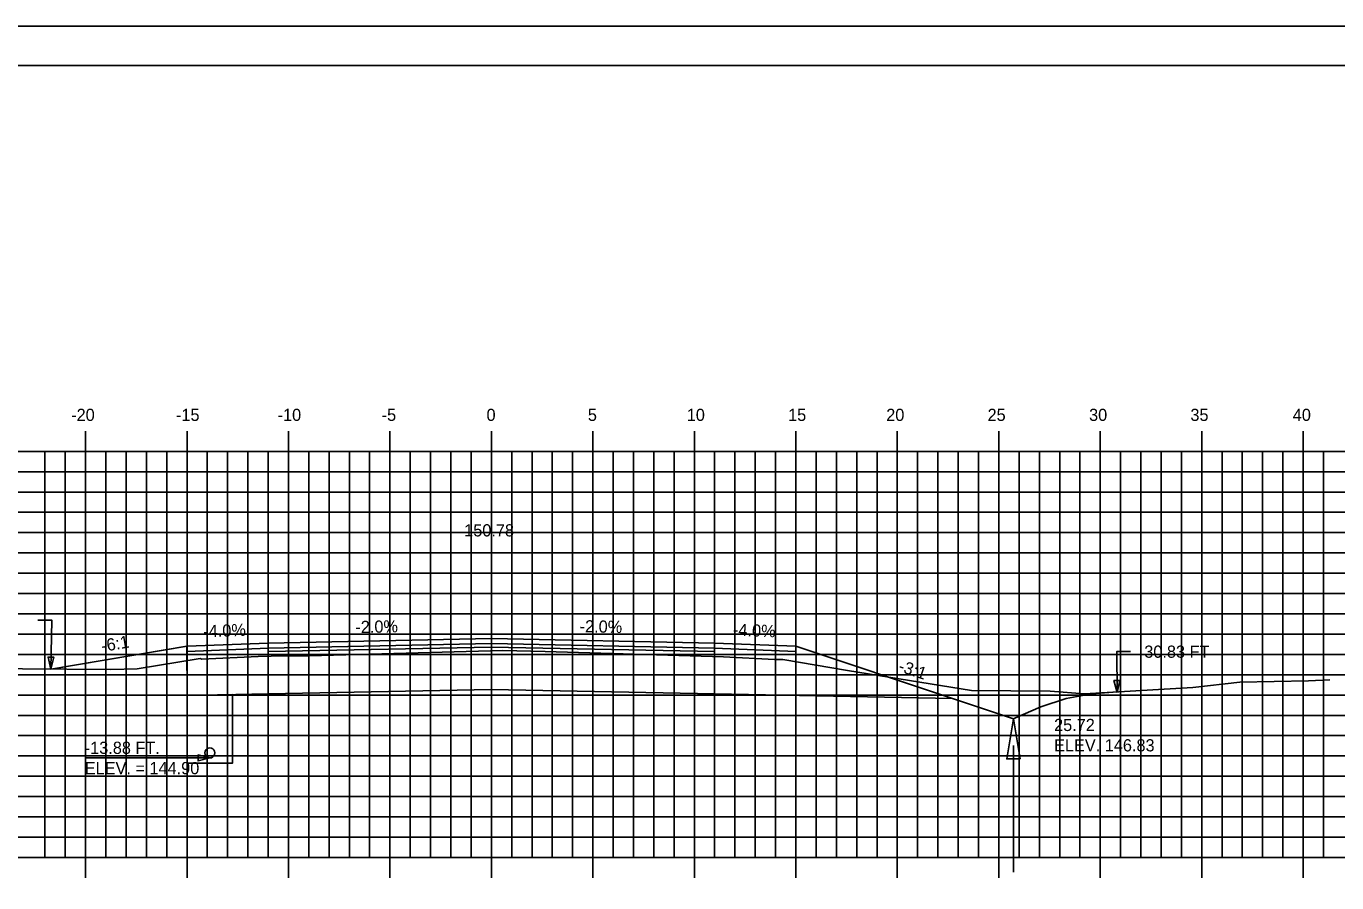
# Model space of a CAD drawing. Extents: x 1147633 to 1147803, y 608981 to 609091.
# Drawn here: x 1147693.5 to 1147758.1, y 609049.1 to 609091.3 of the extents above; entities that cross this region are included whole.
import ezdxf

# ---------------------------------------------------------------- set-up
doc = ezdxf.new("R2010")
doc.units = 0
for name, color, linetype in [('ANNOTATION', 7, 'Continuous'), ('BORDER', 7, 'Continuous'), ('D_Drainage_Ditch_Line', 7, 'Continuous'), ('D_Drainage_Underdrain', 7, 'Continuous'), ('D_Drainage_Underdrain_06in', 7, 'Continuous'), ('D_Roadway_Centerline', 7, 'Continuous'), ('D_Roadway_Centerline_Text', 7, 'Continuous'), ('D_Roadway_Edge_Shoulder', 7, 'Continuous'), ('D_Roadway_Edge_TW', 7, 'Continuous'), ('D_Roadway_Pavement', 7, 'Continuous'), ('D_Roadway_SlopeLines', 7, 'Continuous'), ('D_Roadway_SubGrade', 7, 'Continuous'), ('D_Text_Standard', 7, 'Continuous'), ('H_V ANNOTATION', 7, 'Continuous'), ('MAJOR', 7, 'Continuous'), ('MINOR', 7, 'Continuous'), ('PLOT BOUNDARY', 7, 'Continuous'), ('S_Roadway_Centerline', 7, 'Continuous')]:
    doc.layers.add(name, color=color, linetype=linetype)

msp = doc.modelspace()

# ---------------------------------------------------------------- linework, layer by layer
msp.add_lwpolyline([(1147694.741, 609059.617), (1147701.453, 609060.736), (1147701.454, 609060.736), (1147705.454, 609060.896), (1147716.454, 609061.116), (1147727.454, 609060.896), (1147731.454, 609060.736), (1147739.177, 609058.162), (1147742.177, 609057.162), (1147742.281, 609057.214), (1147743.531, 609057.762), (1147744.781, 609058.158), (1147746.031, 609058.4), (1147747.281, 609058.489)])
at = {"layer": 'BORDER'}
msp.add_lwpolyline([(1147641.454, 608984.335), (1147801.454, 608984.335), (1147801.454, 609089.335), (1147641.454, 609089.335)], close=True, dxfattribs=at)
at = {"layer": 'D_Drainage_Ditch_Line'}
msp.add_line((1147742.178, 609055.85), (1147742.177, 609049.606), dxfattribs=at)
msp.add_lwpolyline([(1147742.506, 609055.193), (1147741.849, 609055.193), (1147742.177, 609057.162)], close=True, dxfattribs=at)
at = {"layer": 'D_Drainage_Underdrain'}
msp.add_lwpolyline([(1147701.454, 609058.316), (1147701.454, 609054.986), (1147703.704, 609054.986), (1147703.704, 609058.361)], close=True, dxfattribs=at)
at = {"layer": 'D_Drainage_Underdrain_06in'}
msp.add_lwpolyline([(1147702.579, 609055.736), (1147702.656, 609055.724), (1147702.726, 609055.689), (1147702.781, 609055.633), (1147702.817, 609055.564), (1147702.829, 609055.486), (1147702.817, 609055.409), (1147702.781, 609055.339), (1147702.726, 609055.284), (1147702.656, 609055.249), (1147702.579, 609055.236), (1147702.502, 609055.249), (1147702.432, 609055.284), (1147702.377, 609055.339), (1147702.341, 609055.409), (1147702.329, 609055.486), (1147702.341, 609055.564), (1147702.377, 609055.633), (1147702.432, 609055.689), (1147702.502, 609055.724)], close=True, dxfattribs=at)
at = {"layer": 'D_Roadway_Edge_Shoulder'}
for points in [[(1147705.454, 609060.896), (1147701.454, 609060.736), (1147701.454, 609060.486), (1147705.454, 609060.646)], [(1147727.454, 609060.896), (1147731.454, 609060.736), (1147731.454, 609060.486), (1147727.454, 609060.646)]]:
    msp.add_lwpolyline(points, close=True, dxfattribs=at)
at = {"layer": 'D_Roadway_Edge_TW'}
msp.add_lwpolyline([(1147705.454, 609060.646), (1147705.454, 609060.896), (1147716.454, 609061.116), (1147727.454, 609060.896), (1147727.454, 609060.646), (1147716.454, 609060.866)], close=True, dxfattribs=at)
at = {"layer": 'D_Roadway_Pavement'}
msp.add_lwpolyline([(1147705.454, 609060.48), (1147705.454, 609060.646), (1147716.454, 609060.866), (1147727.454, 609060.646), (1147727.454, 609060.48), (1147716.454, 609060.7)], close=True, dxfattribs=at)
at = {"layer": 'D_Roadway_SlopeLines'}
for points in [[(1147701.454, 609060.736), (1147694.741, 609059.617)], [(1147739.177, 609058.162), (1147742.177, 609057.162)], [(1147742.177, 609057.162), (1147742.281, 609057.214), (1147743.531, 609057.762), (1147744.781, 609058.158), (1147746.031, 609058.4), (1147747.281, 609058.489)]]:
    msp.add_lwpolyline(points, dxfattribs=at)
at = {"layer": 'D_Roadway_SubGrade'}
for points in [[(1147705.454, 609060.48), (1147705.454, 609060.646), (1147701.454, 609060.486), (1147701.454, 609060.736), (1147701.453, 609060.736), (1147701.454, 609058.316), (1147705.454, 609058.396)], [(1147705.454, 609058.396), (1147705.454, 609060.48), (1147716.454, 609060.7), (1147727.454, 609060.48), (1147727.454, 609058.396), (1147716.454, 609058.616)], [(1147727.454, 609060.48), (1147727.454, 609060.646), (1147731.454, 609060.486), (1147731.454, 609060.736), (1147731.454, 609060.736), (1147739.177, 609058.162), (1147727.454, 609058.396)]]:
    msp.add_lwpolyline(points, close=True, dxfattribs=at)
at = {"layer": 'D_Text_Standard'}
msp.add_line((1147696.416, 609055.236), (1147700.83, 609055.236), dxfattribs=at)
for points in [[(1147694.741, 609059.617), (1147694.786, 609062.026), (1147694.106, 609062.026)], [(1147747.281, 609058.464), (1147747.263, 609060.472), (1147747.943, 609060.472)], [(1147702.579, 609055.236), (1147701.51, 609055.236), (1147700.83, 609055.236)]]:
    msp.add_lwpolyline(points, dxfattribs=at)
for points in [[(1147694.741, 609059.617), (1147694.606, 609060.202), (1147694.897, 609060.197)], [(1147747.281, 609058.464), (1147747.13, 609059.044), (1147747.421, 609059.047)], [(1147702.579, 609055.236), (1147701.997, 609055.091), (1147701.997, 609055.382)]]:
    msp.add_lwpolyline(points, close=True, dxfattribs=at)
at = {"layer": 'MAJOR'}
for p, q in [((1147696.454, 609071.337), (1147696.454, 609070.335)), ((1147701.454, 609071.337), (1147701.454, 609070.335)), ((1147706.454, 609071.337), (1147706.454, 609070.335)), ((1147711.454, 609071.337), (1147711.454, 609070.335)), ((1147716.454, 609071.337), (1147716.454, 609070.335)), ((1147721.454, 609071.337), (1147721.454, 609070.335)), ((1147726.454, 609071.337), (1147726.454, 609070.335)), ((1147731.454, 609071.337), (1147731.454, 609070.335)), ((1147736.454, 609071.337), (1147736.454, 609070.335)), ((1147741.454, 609071.337), (1147741.454, 609070.335)), ((1147746.454, 609071.337), (1147746.454, 609070.335)), ((1147751.454, 609071.337), (1147751.454, 609070.335)), ((1147756.454, 609071.337), (1147756.454, 609070.335)), ((1147646.454, 609070.335), (1147786.454, 609070.335)), ((1147646.454, 609070.335), (1147786.454, 609070.335)), ((1147696.454, 609050.335), (1147696.454, 609070.335)), ((1147701.454, 609050.335), (1147701.454, 609070.335)), ((1147706.454, 609050.335), (1147706.454, 609070.335)), ((1147711.454, 609050.335), (1147711.454, 609070.335)), ((1147716.454, 609050.335), (1147716.454, 609070.335)), ((1147721.454, 609050.335), (1147721.454, 609070.335)), ((1147726.454, 609050.335), (1147726.454, 609070.335)), ((1147731.454, 609050.335), (1147731.454, 609070.335)), ((1147736.454, 609050.335), (1147736.454, 609070.335)), ((1147741.454, 609050.335), (1147741.454, 609070.335)), ((1147746.454, 609050.335), (1147746.454, 609070.335)), ((1147751.454, 609050.335), (1147751.454, 609070.335)), ((1147756.454, 609050.335), (1147756.454, 609070.335)), ((1147646.454, 609065.335), (1147786.454, 609065.335)), ((1147646.454, 609060.335), (1147786.454, 609060.335)), ((1147646.454, 609055.335), (1147786.454, 609055.335)), ((1147646.454, 609050.335), (1147786.454, 609050.335)), ((1147646.454, 609050.335), (1147786.454, 609050.335)), ((1147696.454, 609049.333), (1147696.454, 609050.335)), ((1147701.454, 609049.333), (1147701.454, 609050.335)), ((1147706.454, 609049.333), (1147706.454, 609050.335)), ((1147711.454, 609049.333), (1147711.454, 609050.335)), ((1147716.454, 609049.333), (1147716.454, 609050.335)), ((1147721.454, 609049.333), (1147721.454, 609050.335)), ((1147726.454, 609049.333), (1147726.454, 609050.335)), ((1147731.454, 609049.333), (1147731.454, 609050.335)), ((1147736.454, 609049.333), (1147736.454, 609050.335)), ((1147741.454, 609049.333), (1147741.454, 609050.335)), ((1147746.454, 609049.333), (1147746.454, 609050.335)), ((1147751.454, 609049.333), (1147751.454, 609050.335)), ((1147756.454, 609049.333), (1147756.454, 609050.335))]:
    msp.add_line(p, q, dxfattribs=at)
at = {"layer": 'MINOR'}
for p, q in [((1147694.454, 609050.335), (1147694.454, 609070.335)), ((1147695.454, 609050.335), (1147695.454, 609070.335)), ((1147697.454, 609050.335), (1147697.454, 609070.335)), ((1147698.454, 609050.335), (1147698.454, 609070.335)), ((1147699.454, 609050.335), (1147699.454, 609070.335)), ((1147700.454, 609050.335), (1147700.454, 609070.335)), ((1147702.454, 609050.335), (1147702.454, 609070.335)), ((1147703.454, 609050.335), (1147703.454, 609070.335)), ((1147704.454, 609050.335), (1147704.454, 609070.335)), ((1147705.454, 609050.335), (1147705.454, 609070.335)), ((1147707.454, 609050.335), (1147707.454, 609070.335)), ((1147708.454, 609050.335), (1147708.454, 609070.335)), ((1147709.454, 609050.335), (1147709.454, 609070.335)), ((1147710.454, 609050.335), (1147710.454, 609070.335)), ((1147712.454, 609050.335), (1147712.454, 609070.335)), ((1147713.454, 609050.335), (1147713.454, 609070.335)), ((1147714.454, 609050.335), (1147714.454, 609070.335)), ((1147715.454, 609050.335), (1147715.454, 609070.335)), ((1147717.454, 609050.335), (1147717.454, 609070.335)), ((1147718.454, 609050.335), (1147718.454, 609070.335)), ((1147719.454, 609050.335), (1147719.454, 609070.335)), ((1147720.454, 609050.335), (1147720.454, 609070.335)), ((1147722.454, 609050.335), (1147722.454, 609070.335)), ((1147723.454, 609050.335), (1147723.454, 609070.335)), ((1147724.454, 609050.335), (1147724.454, 609070.335)), ((1147725.454, 609050.335), (1147725.454, 609070.335)), ((1147727.454, 609050.335), (1147727.454, 609070.335)), ((1147728.454, 609050.335), (1147728.454, 609070.335)), ((1147729.454, 609050.335), (1147729.454, 609070.335)), ((1147730.454, 609050.335), (1147730.454, 609070.335)), ((1147732.454, 609050.335), (1147732.454, 609070.335)), ((1147733.454, 609050.335), (1147733.454, 609070.335)), ((1147734.454, 609050.335), (1147734.454, 609070.335)), ((1147735.454, 609050.335), (1147735.454, 609070.335)), ((1147737.454, 609050.335), (1147737.454, 609070.335)), ((1147738.454, 609050.335), (1147738.454, 609070.335)), ((1147739.454, 609050.335), (1147739.454, 609070.335)), ((1147740.454, 609050.335), (1147740.454, 609070.335)), ((1147742.454, 609050.335), (1147742.454, 609070.335)), ((1147743.454, 609050.335), (1147743.454, 609070.335)), ((1147744.454, 609050.335), (1147744.454, 609070.335)), ((1147745.454, 609050.335), (1147745.454, 609070.335)), ((1147747.454, 609050.335), (1147747.454, 609070.335)), ((1147748.454, 609050.335), (1147748.454, 609070.335)), ((1147749.454, 609050.335), (1147749.454, 609070.335)), ((1147750.454, 609050.335), (1147750.454, 609070.335)), ((1147752.454, 609050.335), (1147752.454, 609070.335)), ((1147753.454, 609050.335), (1147753.454, 609070.335)), ((1147754.454, 609050.335), (1147754.454, 609070.335)), ((1147755.454, 609050.335), (1147755.454, 609070.335)), ((1147757.454, 609050.335), (1147757.454, 609070.335)), ((1147646.454, 609069.335), (1147786.454, 609069.335)), ((1147646.454, 609068.335), (1147786.454, 609068.335)), ((1147646.454, 609067.335), (1147786.454, 609067.335)), ((1147646.454, 609066.335), (1147786.454, 609066.335)), ((1147646.454, 609064.335), (1147786.454, 609064.335)), ((1147646.454, 609063.335), (1147786.454, 609063.335)), ((1147646.454, 609062.335), (1147786.454, 609062.335)), ((1147646.454, 609061.335), (1147786.454, 609061.335)), ((1147646.454, 609059.335), (1147786.454, 609059.335)), ((1147646.454, 609058.335), (1147786.454, 609058.335)), ((1147646.454, 609057.335), (1147786.454, 609057.335)), ((1147646.454, 609056.335), (1147786.454, 609056.335)), ((1147646.454, 609054.335), (1147786.454, 609054.335)), ((1147646.454, 609053.335), (1147786.454, 609053.335)), ((1147646.454, 609052.335), (1147786.454, 609052.335)), ((1147646.454, 609051.335), (1147786.454, 609051.335))]:
    msp.add_line(p, q, dxfattribs=at)
at = {"layer": 'PLOT BOUNDARY'}
msp.add_lwpolyline([(1147633.361, 608981.276), (1147803.361, 608981.276), (1147803.361, 609091.276), (1147633.361, 609091.276)], close=True, dxfattribs=at)
at = {"layer": 'S_Roadway_Centerline'}
msp.add_lwpolyline([(1147691.167, 609059.648), (1147697.698, 609059.592), (1147698.991, 609059.628), (1147702.107, 609060.13), (1147702.192, 609060.108), (1147704.962, 609060.226), (1147705.601, 609060.245), (1147707.498, 609060.272), (1147717.006, 609060.535), (1147719.096, 609060.48), (1147727.883, 609060.223), (1147730.396, 609060.091), (1147730.812, 609060.086), (1147734.004, 609059.548), (1147740.109, 609058.553), (1147743.987, 609058.523), (1147745.683, 609058.397), (1147751.01, 609058.704), (1147753.338, 609058.975), (1147756.707, 609059.043), (1147757.762, 609059.083)], dxfattribs=at)

# ---------------------------------------------------------------- texts
at = {"layer": 'ANNOTATION'}
for s, rotation, p in [('-2.0%', 1.14576, (1147709.757, 609061.383)), ('-2.0%', 358.85424, (1147720.797, 609061.43)), ('-4.0%', 2.29061, (1147702.27, 609061.17)), ('-4.0%', 357.70939, (1147728.35, 609061.261)), ('-6:1', 9.46362, (1147697.276, 609060.454)), ('-3:1', 341.56521, (1147736.465, 609059.52))]:
    msp.add_text(s, height=0.6, rotation=rotation, dxfattribs=at).set_placement(p)
at = {"layer": 'D_Roadway_Centerline'}
for s, p in [('C', (1147716.449, 609061.116)), ('L', (1147716.454, 609061.109))]:
    msp.add_text(s, height=0.0146, dxfattribs=at).set_placement(p)
at = {"layer": 'D_Roadway_Centerline_Text'}
msp.add_text('150.78', height=0.6, dxfattribs=at).set_placement((1147715.113, 609066.148))
at = {"layer": 'D_Text_Standard'}
for s, p in [('30.83 FT', (1147748.623, 609060.172)), ('25.72', (1147744.178, 609056.562)), ('ELEV. 146.83', (1147744.178, 609055.56)), ('-13.88 FT.', (1147696.416, 609055.436)), ('ELEV. = 144.90', (1147696.416, 609054.436))]:
    msp.add_text(s, height=0.6, dxfattribs=at).set_placement(p)
at = {"layer": 'H_V ANNOTATION'}
for s, p in [('-20', (1147695.747, 609071.835)), ('-15', (1147700.911, 609071.835)), ('-10', (1147705.919, 609071.835)), ('-5', (1147711.045, 609071.835)), ('0', (1147716.213, 609071.835)), ('5', (1147721.205, 609071.835)), ('10', (1147726.079, 609071.835)), ('15', (1147731.071, 609071.835)), ('20', (1147735.908, 609071.835)), ('25', (1147740.9, 609071.835)), ('30', (1147745.903, 609071.835)), ('35', (1147750.895, 609071.835)), ('40', (1147755.94, 609071.835))]:
    msp.add_text(s, height=0.6, dxfattribs=at).set_placement(p)
at = {"layer": 'S_Roadway_Centerline'}
for s, p in [('C', (1147717.001, 609060.535)), ('L', (1147717.006, 609060.528))]:
    msp.add_text(s, height=0.0146, dxfattribs=at).set_placement(p)

doc.saveas('drawing.dxf')
